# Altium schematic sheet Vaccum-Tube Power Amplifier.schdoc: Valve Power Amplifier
size A4; Organization: Altium Limited; Address1: L3, 12a Rodborough Rd; Address2: Frenchs Forest; Address3: NSW; Address4: Australia 2086; DocumentNumber: 1; SheetNumber: 1; SheetTotal: 1
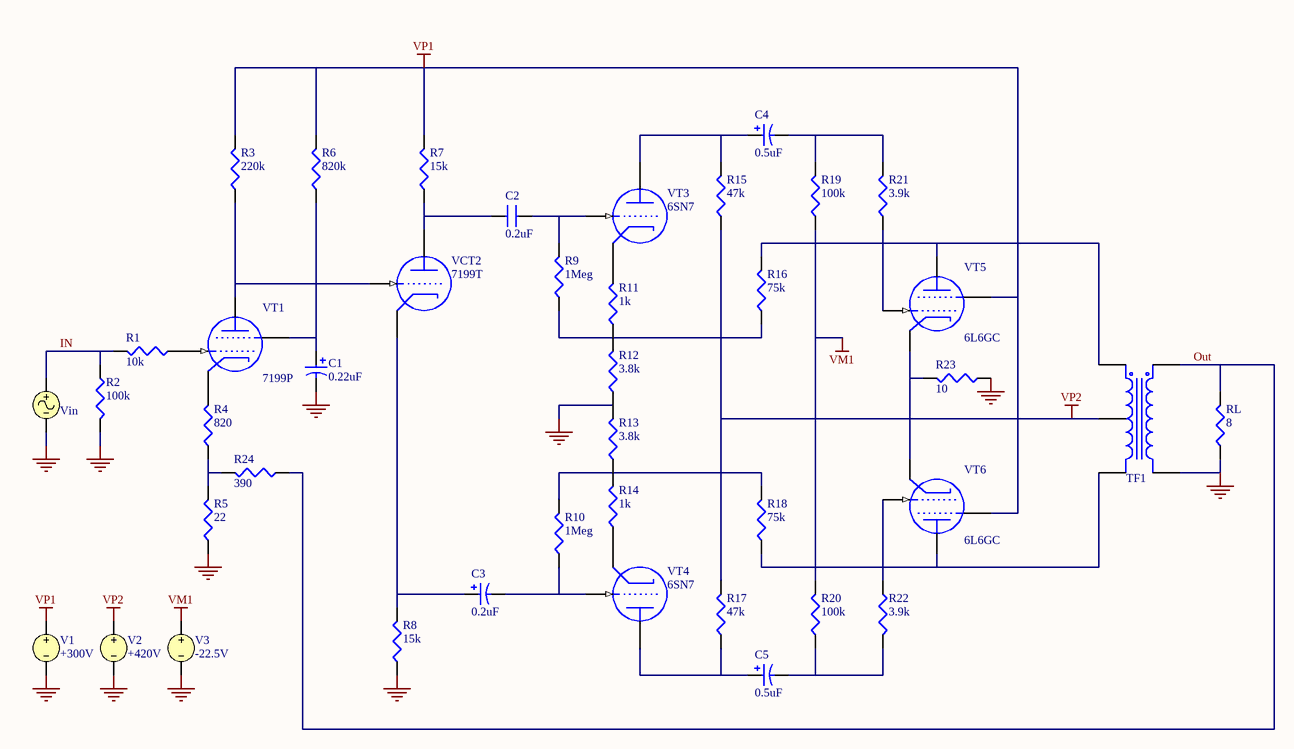
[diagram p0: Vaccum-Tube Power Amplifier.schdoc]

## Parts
C1  0.22uF
C2  0.2uF
C3  0.2uF
C4  0.5uF
C5  0.5uF
R1  10k
R2  100k
R3  220k
R4  820
R5  22
R6  820k
R7  15k
R8  15k
R9  1Meg
R10  1Meg
R11  1k
R12  3.8k
R13  3.8k
R14  1k
R15  47k
R16  75k
R17  47k
R18  75k
R19  100k
R20  100k
R21  3.9k
R22  3.9k
R23  10
R24  390
RL  8
TF1  TRANSFORMERCT  (value not drawn)
V1  +300V
V2  +420V
V3  -22.5V
VCT2  7199T
Vin  VSIN  (value not drawn)
VT1  7199P
VT3  6SN7
VT4  6SN7
VT5  6L6GC
VT6  6L6GC

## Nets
GND: C1.2 R2.1(TOP) R5.2(BOT) R8.2(BOT) R12.2(BOT) R13.1(TOP) R23.2(BOT) RL.2(BOT) TF1.2(Pri-) V1.2 V2.2 V3.2 Vin.2
VM1: R19.2(BOT) R20.1(TOP) V3.1
VP1: R3.1(TOP) R6.1(TOP) R7.1(TOP) V1.1 VT5.2(SCRG) VT6.2(SCRG)
VP2: R15.2(BOT) R17.1(TOP) TF1.4(SecCT) V2.1
IN: R1.1(TOP) R2.2(BOT) Vin.1
Out: R24.2(BOT) RL.1(TOP) TF1.1(Pri+)
NetC1_1: C1.1 R6.2(BOT) VT1.2(SCRG)
NetC2_1: C2.1 R7.2(BOT) VCT2.1(P)
NetC2_2: C2.2 R9.1(TOP) VT3.2(G)
NetC3_1: C3.1 R8.1(TOP) VCT2.3(K)
NetC3_2: C3.2 R10.2(BOT) VT4.2(G)
NetC4_1: C4.1 R15.1(TOP) VT3.1(P)
NetC4_2: C4.2 R19.1(TOP) R21.1(TOP)
NetC5_1: C5.1 R17.2(BOT) VT4.1(P)
NetC5_2: C5.2 R20.2(BOT) R22.1(TOP)
NetR1_2: R1.2(BOT) VT1.3(CTLG)
NetR3_2: R3.2(BOT) VCT2.2(G) VT1.1(P)
NetR4_1: R4.1(TOP) VT1.4(K)
NetR4_2: R4.2(BOT) R5.1(TOP) R24.1(TOP)
NetR9_2: R9.2(BOT) R11.2(BOT) R12.1(TOP) R16.2(BOT)
NetR10_1: R10.1(TOP) R13.2(BOT) R14.1(TOP) R18.1(TOP)
NetR11_1: R11.1(TOP) VT3.3(K)
NetR14_2: R14.2(BOT) VT4.3(K)
NetR16_1: R16.1(TOP) TF1.3(Sec+) VT5.1(P)
NetR18_2: R18.2(BOT) TF1.5(Sec-) VT6.1(P)
NetR21_2: R21.2(BOT) VT5.3(CTLG)
NetR22_2: R22.2(BOT) VT6.3(CTLG)
NetR23_1: R23.1(TOP) VT5.4(K) VT6.4(K)

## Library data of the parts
C1 C3-C5 = CAP2: Bi-Polar Capacitor
C2 = CAP: Capacitor
R1-R24 RL = RES: Resistor
TF1 = TRANSFORMERCT: CT Transformer (Coupled Inductor Model)
V1-V3 = VSRC: Voltage Source
VCT2 = 7199T: Triode
Vin = VSIN: Sinusoidal Voltage Source
VT1 = 7199P: Tetrode
VT3 VT4 = 6SN7: Triode
VT5 VT6 = 6L6GC: Tetrode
